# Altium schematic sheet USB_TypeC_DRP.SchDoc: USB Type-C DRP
size A3; DocumentNumber: 13; Revision: A-01; SheetNumber: 13; SheetTotal: 17; Project: STM32MP15-BATTERY BOARD
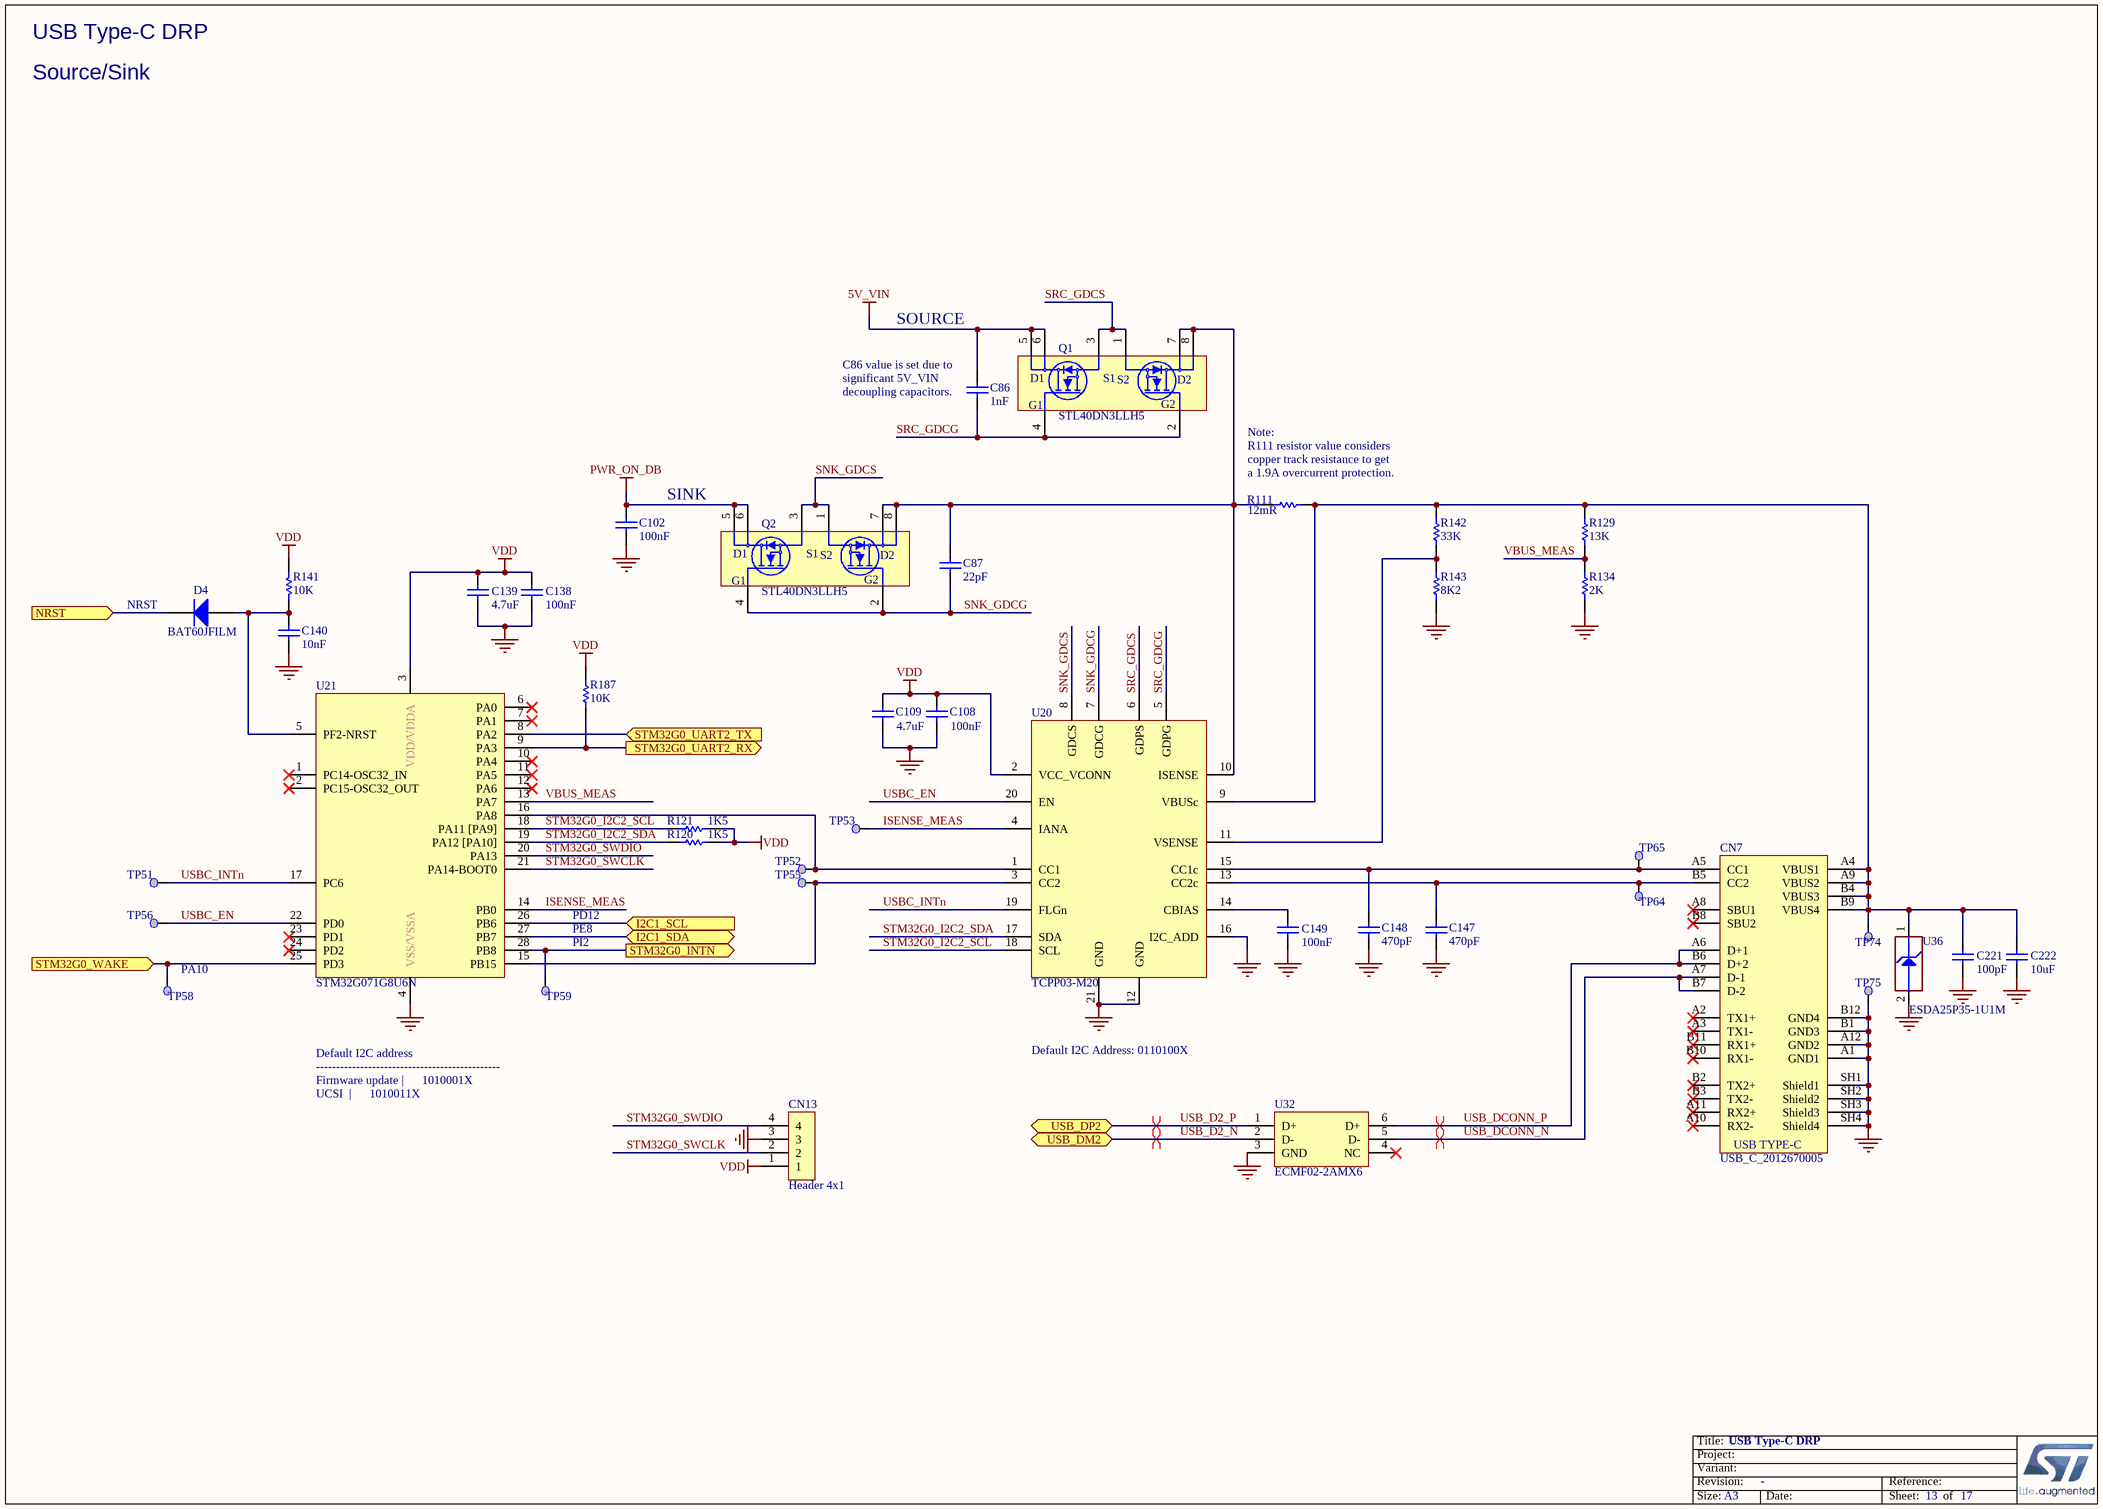
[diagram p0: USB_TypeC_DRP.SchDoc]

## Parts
C86  value 1nF  [C0402]  (hidden comment: Capacitor)
C87  value 22pF  [C0402]  (hidden comment: Capacitor)
C102  value 100nF  [C0402]  (hidden comment: Capacitor)
C108  value 100nF  [C0402]  (hidden comment: Capacitor)
C109  value 4.7uF  [C0402]  (hidden comment: Capacitor)
C138  value 100nF  [C0402]  (hidden comment: Capacitor)
C139  value 4.7uF  [C0402]  (hidden comment: Capacitor)
C140  value 10nF  [C0402]  (hidden comment: Capacitor)
C147  value 470pF  [C0402]  (hidden comment: Capacitor)
C148  value 470pF  [C0402]  (hidden comment: Capacitor)
C149  value 100nF  [C0603]  (hidden comment: Capacitor)
C221  value 100pF  [C0402]  (hidden comment: Capacitor)
C222  value 10uF  [C1210]  (hidden comment: Capacitor)
CN7  value USB_C_2012670005  [CON_USB-TYPEC_MOLEX_2012670005]  (hidden comment: USB_TYPE_C_Receptacle)
CN13  Header 4x1  [CON_SAMTEC_TSW-104-07-G-S]
D4  BAT60JFILM  [DIO_SOD323]
Q1  STL40DN3LLH5  [PowerFLAT_5x6]
Q2  STL40DN3LLH5  [PowerFLAT_5x6]
R111  value 12mR  [R0603_H070]  (hidden comment: Resistor)
R120  value 1K5  [R0402]  (hidden comment: Resistor)
R121  value 1K5  [R0402]  (hidden comment: Resistor)
R129  value 13K  [R0603]  (hidden comment: Resistor)
R134  value 2K  [R0603]  (hidden comment: Resistor)
R141  value 10K  [R0402]  (hidden comment: Resistor)
R142  value 33K  [R0603]  (hidden comment: Resistor)
R143  value 8K2  [R0603]  (hidden comment: Resistor)
R187  value 10K  [R0402]  (hidden comment: Resistor)
TP51  Test Point  [TP_SMD_1MM]  (value not drawn)  (no BOM)
TP52  Test Point  [TP_SMD_1MM]  (value not drawn)  (no BOM)
TP53  Test Point  [TP_SMD_1MM]  (value not drawn)  (no BOM)
TP55  Test Point  [TP_SMD_1MM]  (value not drawn)  (no BOM)
TP56  Test Point  [TP_SMD_1MM]  (value not drawn)  (no BOM)
TP58  Test Point  [TP_SMD_1MM]  (value not drawn)  (no BOM)
TP59  Test Point  [TP_SMD_1MM]  (value not drawn)  (no BOM)
TP64  Test Point  [TP_SMD_1MM]  (value not drawn)  (no BOM)
TP65  Test Point  [TP_SMD_1MM]  (value not drawn)  (no BOM)
TP74  Test Point  [TP_SMD_1MM]  (value not drawn)  (no BOM)
TP75  Test Point  [TP_SMD_1MM]  (value not drawn)  (no BOM)
U20  TCPP03-M20  [ICC_QFN20-EPAD_4X4_P050]
U21  STM32G071G8U6N  [ICC_UFQFPN28_4X4_P050]
U32  ECMF02-2AMX6  [ESD_QFN-6L_1P7X1P5_P050]
U36  value ESDA25P35-1U1M  [ESD_QFN1610_2N_1K_2A]  (hidden comment: ESD-TRANSIL)

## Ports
I2C1_SCL (in), I2C1_SDA (bidir), NRST (in), STM32G0_INTN (out), STM32G0_UART2_RX (out), STM32G0_UART2_TX (in), STM32G0_WAKE (in), USB_DM2 (bidir), USB_DP2 (bidir)

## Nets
5V_VIN: C86.2 Q1.5(D1) Q1.6(D1)
GND: C102.1 C108.1 C109.1 C138.1 C139.1 C140.1 C147.1 C148.1 C149.1 C221.1 C222.1 CN7.A1(GND1) CN7.A12(GND2) CN7.B1(GND3) CN7.B12(GND4) CN7.SH1(Shield1) CN7.SH2(Shield2) CN7.SH3(Shield3) CN7.SH4(Shield4) CN13.3 R134.1 R143.1 TP75.1 U20.12(GND) U20.16(I2C_ADD) U20.21(GND) U21.4(VSS/VSSA) U32.3(GND) U36.2(GND)
PWR_ON_DB: C102.2 Q2.5(D1) Q2.6(D1)
VDD: C108.2 C109.2 C138.2 C139.2 CN13.1 R120.2 R121.1 R141.2 R187.2 U20.2(VCC_VCONN) U21.3(VDD/VDDA)
I2C1_SCL: U21.26(PB6) ; port I2C1_SCL
I2C1_SDA: U21.27(PB7) ; port I2C1_SDA
ISENSE_MEAS: TP53.1 U20.4(IANA) U21.14(PB0)
NRST: D4.2(K) ; port NRST
SNK_GDCG: C87.1 Q2.2(G2) Q2.4(G1) U20.7(GDCG)
SNK_GDCS: Q2.1(S2) Q2.3(S1) U20.8(GDCS)
SRC_GDCG: C86.1 Q1.2(G2) Q1.4(G1) U20.5(GDPG)
SRC_GDCS: Q1.1(S2) Q1.3(S1) U20.6(GDPS)
STM32G0_I2C2_SCL: R121.2 U20.18(SCL) U21.18(PA11_[PA9])
STM32G0_I2C2_SDA: R120.1 U20.17(SDA) U21.19(PA12_[PA10])
STM32G0_INTN: TP59.1 U21.28(PB8) ; port STM32G0_INTN
STM32G0_SWCLK: CN13.2 U21.21(PA14-BOOT0)
STM32G0_SWDIO: CN13.4 U21.20(PA13)
STM32G0_UART2_RX: R187.1 U21.9(PA3) ; port STM32G0_UART2_RX
STM32G0_UART2_TX: U21.8(PA2) ; port STM32G0_UART2_TX
STM32G0_WAKE: TP58.1 U21.25(PD3) ; port STM32G0_WAKE
USB_D2_N: U32.2(D-) ; port USB_DM2
USB_D2_P: U32.1(D+) ; port USB_DP2
USB_DCONN_N: CN7.A7(D-1) CN7.B7(D-2) U32.5(D-)
USB_DCONN_P: CN7.A6(D+1) CN7.B6(D+2) U32.6(D+)
USBC_EN: TP56.1 U20.20(EN) U21.22(PD0)
USBC_INTn: TP51.1 U20.19(FLGn) U21.17(PC6)
VBUS_MEAS: R129.1 R134.2 U21.13(PA7)
NetC87_2: C87.2 Q1.7(D2) Q1.8(D2) Q2.7(D2) Q2.8(D2) R111.2 U20.10(ISENSE)
NetC140_2: C140.2 D4.1(A) R141.1 U21.5(PF2-NRST)
NetC147_2: C147.2 CN7.B5(CC2) TP64.1 U20.13(CC2c)
NetC148_2: C148.2 CN7.A5(CC1) TP65.1 U20.15(CC1c)
NetC149_2: C149.2 U20.14(CBIAS)
NetC221_2: C221.2 C222.2 CN7.A4(VBUS1) CN7.A9(VBUS2) CN7.B4(VBUS3) CN7.B9(VBUS4) R111.1 R129.2 R142.2 TP74.1 U20.9(VBUSc) U36.1(IO1)
NetR142_1: R142.1 R143.2 U20.11(VSENSE)
NetTP52_1: TP52.1 U20.1(CC1) U21.16(PA8)
NetTP55_1: TP55.1 U20.3(CC2) U21.15(PB15)

Not connected (* = marked no-connect by the designer): CN7 A2(TX1+)* A3(TX1-)* A8(SBU1)* A10(RX2-)* A11(RX2+)* B2(TX2+)* B3(TX2-)* B8(SBU2)* B10(RX1-)* B11(RX1+)*; U21 1(PC14-OSC32_IN)* 2(PC15-OSC32_OUT)* 6(PA0)* 7(PA1)* 10(PA4)* 11(PA5)* 12(PA6)* 23(PD1)* 24(PD2)*; U32 4(NC)*

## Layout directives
differential pair: USB_D2_N, USB_D2_P, USB_DCONN_N, USB_DCONN_P

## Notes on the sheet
- USB Type-C DRP
- Source/Sink
- SOURCE
- (near C86) C86 value is set due to significant 5V_VIN decoupling capacitors.
- SINK
- (near R111) Note:
  R111 resistor value considers copper track resistance to get a 1.9A overcurrent protection.
- (near D4) NRST
- PD12
- (near TP58) PA10
- PE8
- PI2
- Default I2C Address: 0110100X
- Default I2C address
  ----------------------------------------------
  Firmware update	|      1010001X
  UCSI		|      1010011X

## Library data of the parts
C86 = MCD-00198: Capacitor, MLCC, 1nF, 16V, X7R, +/-10%, 0402, T=0.5mm; Part_Preference: Recommended; Manufacturer: YAGEO; Manufacturer_Part_Number: CC0402KRX7R7BB102; Component_Country_Of_Origin: China; ShowFields: YES; ID: 2665
C87 = MCD-01995: Capacitor, MLCC, 22pF, 50V, C0G, +/-5%, 0402, T=0.5mm; Part_Preference: Recommended; Manufacturer: TDK; Manufacturer_Part_Number: C1005NP01H220J050BA; Partial_Alternate_Internal_Part_Number: MCD-04601; Component_Country_Of_Origin: Unknown; ShowFields: YES; ID: 4095
C102 C108 C138 = MCD-00006: Capacitor, MLCC, 100nF, 16V, X7R, +/-10%, 0402, T=0.5mm; Part_Preference: Recommended; Manufacturer: YAGEO; Manufacturer_Part_Number: CC0402KRX7R7BB104; Partial_Alternate_Internal_Part_Number: MCD-03299; Order_Code_RS: 9402047; Component_Country_Of_Origin: China; ShowFields: YES; ID: 2474
C109 C139 = MCD-01356: Capacitor, MLCC, 4.7uF, 6V3, X5R, +/-20%, 0402, T=0.5mm; Part_Preference: Recommended; Manufacturer: MURATA; Manufacturer_Part_Number: GRM155R60J475ME47; Partial_Alternate_Internal_Part_Number: MCD-04455; Order_Code_RS: 814-5230; Component_Country_Of_Origin: Japan°°; ShowFields: YES; ID: 3456
C140 = MCD-02198: Capacitor, MLCC, 10nF, 50V, X7R, +/-10%, 0402, T=0.5mm; Part_Preference: Recommended; Manufacturer: YAGEO; Manufacturer_Part_Number: CC0402KRX7R9BB103; Order_Code_RS: 6169644; Component_Country_Of_Origin: China; ShowFields: YES; ID: 4298
C147 C148 = MCD-00724: Capacitor, MLCC, 470pF, 50V, NPO, +/-5%, 0402, T=0.5mm; Manufacturer_Part_Number: CC0402JRNPO9BN471; Manufacturer: YAGEO; Part_Preference: Recommended; Order_Code_RS: 199-2186; Component_Country_Of_Origin: China; ShowFields: YES; ID: 3023
C149 = MCD-01099: Capacitor, MLCC, 100nF, 50V, X7R, +/-10%, 0603, T=0.8mm; BMS_Part_Number: 9142278; Part_Preference: Recommended; Manufacturer: YAGEO; Manufacturer_Part_Number: CC0603KRX7R9BB104; Order_Code_RS: 669-8767; Component_Country_Of_Origin: China; ShowFields: YES; ID: 3397
C221 = MCD-00205: Capacitor, MLCC, 100pF, 50V, NPO, +/-5%, 0402, T=0.5mm; Manufacturer_Part_Number: CC0402JRNPO9BN101; Manufacturer: YAGEO; Part_Preference: Recommended; Component_Country_Of_Origin: China; ShowFields: YES; ID: 2658
C222 = MCD-02378: Capacitor, MLCC, 10uF, 50V, X7R, +/-10%, 1210, T=2.5mm; Manufacturer_Part_Number: C3225X7R1H106K250AC; Manufacturer: TDK; Part_Preference: Recommended; Partial_Alternate_Internal_Part_Number: MCD-04210; Component_Country_Of_Origin: Japan°; ShowFields: YES; ID: 4484
CN7 = MCD-02421: USB_TypeC, 24 pins, RA, SMD, T=3.71mm (USB Certified 3.1); Part_Type: Connector; Manufacturer_Part_Number: 2012670005; Manufacturer: MOLEX; Part_Preference: Recommended; Order_Code_RS: 176-8434; Component_Country_Of_Origin: Unknown; ShowFields: YES; ID: 4527
CN13 = MCD-00029: Header, 4x1, 2.54mm, VR, TH, T=5.84mm/2.54mm; Part_Type: Connector; Manufacturer_Part_Number: TSW-104-07-G-S; Manufacturer: SAMTEC; Part_Preference: Recommended; Partial_Alternate_Internal_Part_Number: MCD-04227; Order_Code_RS: 161-2460; Component_Country_Of_Origin: China, Costa Rica, Malaysia, USA, Vietnam; ShowFields: YES; ID: 2487
D4 = MCD-00034: BMS_Part_Number: 9151097; Part_Preference: Recommended; Part_Type: Diode; Manufacturer: STMICROELECTRONICS; Manufacturer_HQ_COO: EU; Component_Country_Of_Origin: China; ShowFields: YES; ID: 2483; Order_Code_RS: 714-6879
Q1 Q2 = MCD-02152: MOSFET, Dual N-channel 30 V, 0.016 Ω typ., 40 A, STripFET™ H5 Power MOSFET; Part_Preference: Recommended; Part_Type: Transistor; Manufacturer: STMICROELECTRONICS; Manufacturer_HQ_COO: EU; Component_Country_Of_Origin: China; ShowFields: YES; ID: 4252
R111 = MCD-03129: Resistor, 12mR, 0603, +/-1%, 1/2W; Part_Preference: Recommended; Manufacturer: VISHAY; Manufacturer_Part_Number: WFCP0603R0120FE66; ShowFields: YES; ID: 5245; Component_Country_Of_Origin: Taiwan°
R120 R121 = MCD-00068: Resistor, 1K5, 0402, +/-1%, 1/16W; Part_Preference: Recommended; Manufacturer: YAGEO; Manufacturer_Part_Number: RC0402FR-071K5L; Order_Code_RS: 9239251; Component_Country_Of_Origin: China; ShowFields: YES; ID: 2524
R129 = MCD-00384: Resistor, 13K, 0603,+/-1%, 1/10W; Part_Preference: Recommended; Manufacturer: YAGEO; Manufacturer_Part_Number: RC0603FR-0713KL; Component_Country_Of_Origin: China; ShowFields: YES; ID: 2894
R134 = MCD-00420: Resistor, 2K ,0603, +/-1%, 1/10W; Part_Preference: Recommended; Manufacturer: YAGEO; Manufacturer_Part_Number: RC0603FR-072KL; Component_Country_Of_Origin: China; ShowFields: YES; ID: 2857
R141 = MCD-00053: Resistor, 10K, 0402, +/-1%, 1/16W; BMS_Part_Number: 9131590; Part_Preference: Recommended; Manufacturer: YAGEO; Manufacturer_Part_Number: RC0402FR-0710KL; Order_Code_RS: 9239359; Component_Country_Of_Origin: China; ShowFields: YES; ID: 2539
R142 = MCD-00259: Resistor, 33K, 0603, +/-1%, 1/10W; BMS_Part_Number: 9129771; Part_Preference: Recommended; Manufacturer: YAGEO; Manufacturer_Part_Number: RC0603FR-0733KL; Component_Country_Of_Origin: China; ShowFields: YES; ID: 2610
R143 = MCD-00530: Resistor, 8K2, 0603, +/-1%, 1/10W; Part_Preference: Recommended; Manufacturer: YAGEO; Manufacturer_Part_Number: RC0603FR-078K2L; Component_Country_Of_Origin: China; ShowFields: YES; ID: 3212
R187 = MCD-00053: Resistor, 10K, 0402, +/-1%, 1/16W; Manufacturer_Part_Number: RC0402FR-0710KL; Manufacturer: YAGEO; BMS_Part_Number: 9131590; Part_Preference: Recommended; Order_Code_RS: 9239359; Component_Country_Of_Origin: China; ShowFields: YES; ID: 2539
TP51-TP53 TP55 TP56 TP58 TP59 TP64 TP65 TP74 TP75 = MCD-00074: Test Point 1mm; Part_Type: Misc; Part_Preference: Recommended; ShowFields: YES; ID: 2518; Component_Country_Of_Origin: Unknown
U20 = MCD-02130: USB Type-C Port Protection for USB DRP Power Delivery, PPS compliant; Part_Preference: Recommended; Part_Type: IC; Manufacturer: STMICROELECTRONICS; Manufacturer_HQ_COO: EU; Component_Country_Of_Origin: China; ShowFields: YES; ID: 4230
U21 = MCD-02218: Arm Cortex-M0+ 32-bit MCU, up to 128 KB Flash, 36 KB RAM,  4x USART, timers, ADC, DAC, comm. I/Fs, 1.7-3.6V; Part_Preference: Recommended; Part_Type: IC; Manufacturer: STMICROELECTRONICS; Manufacturer_HQ_COO: EU; Component_Country_Of_Origin: China; ShowFields: YES; ID: 4318
U32 = MCD-00649: Common mode filter with ESD protection for USB 2.0 interface; Part_Type: Diode; Manufacturer: STMICROELECTRONICS; BMS_Part_Number: 9151138; Part_Preference: Recommended; Manufacturer_HQ_COO: EU; Component_Country_Of_Origin: China; ShowFields: YES; ID: 3094; Order_Code_RS: 880-5276
U36 = MCD-01207: High power Transient voltage suppressor:25V/35A EOS and ESD transients protection.; Part_Type: Diode; Manufacturer: STMICROELECTRONICS; Part_Preference: Recommended; Manufacturer_HQ_COO: EU; BMS_Part_Number: 9179045; Component_Country_Of_Origin: China; ShowFields: YES; ID: 3289; Order_Code_RS: 163-9774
